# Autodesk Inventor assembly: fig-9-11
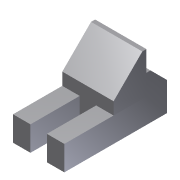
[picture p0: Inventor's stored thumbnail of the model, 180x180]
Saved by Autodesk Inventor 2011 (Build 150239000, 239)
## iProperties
Shininess: 64.0
Length Units: 11269
Angle Units: 11279
Time Units: 11290
Mass Units: 11283
Length Display Precision: 3
Angle Display Precision: 2
Created: 2002-01
Part Number: fig-9-11
Document SubType Name: Assembly
Designer: ***
Density: 0.0
Volumn: 0.0
Area: 0.0
PropertySet Name: Model Information
Control State: 0
Master: False
Checked Out: False
Author: ***
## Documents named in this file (3)
- C:\Users\CADSoft\Desktop\part files\c09-inv-2011-prt\fig-9-11.iam
- C:\Users\CADSoft\Desktop\inventor\c09-inv-2010-prt\c09\Part3.ipt
- C:\Users\CADSoft\Desktop\inventor\c09-inv-2010-prt\c09\Part4.ipt
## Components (2 placed, 2 different names)
1. Part3:1 — Mate:1
2. Part4:1 — Mate:1
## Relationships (1: Mate 1)
- Mate:1: Part3:1 ↔ Part4:1
